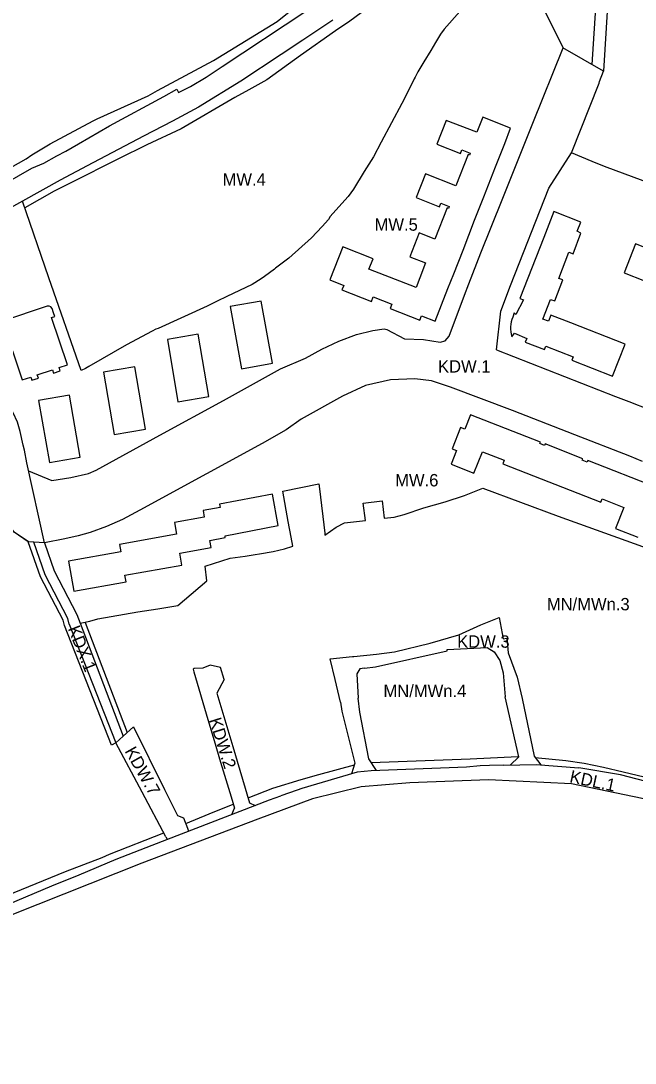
# Model space of a CAD drawing. Extents: x 7427074 to 7428708, y 5545888 to 5547145.
# Drawn here: x 7427353.4 to 7427601.2, y 5545928.9 to 5546349.6 of the extents above; entities that cross this region are included whole.
import ezdxf

# ---------------------------------------------------------------- set-up
doc = ezdxf.new("R2010")
doc.units = 0
for name, color, linetype in [('linie_rozgraniczajace', 7, 'Continuous'), ('linie_zabudowy_nieprzekraczalne', 7, 'Continuous'), ('linie_zabudowy_obowiazujace', 7, 'Continuous'), ('oznaczenia_przeznaczen', 7, 'Continuous')]:
    doc.layers.add(name, color=color, linetype=linetype)

msp = doc.modelspace()

# ---------------------------------------------------------------- linework, layer by layer
at = {"layer": 'linie_rozgraniczajace'}
for p, q in [((7427585.66, 5546361.85), (7427583.79, 5546331.94)), ((7427572.14, 5546338.65), (7427565.07, 5546353.09)), ((7427372.96, 5546106.11), (7427391.75, 5546058.22)), ((7427550.07, 5546094.44), (7427553.7, 5546084.74)), ((7427554.32, 5546052.55), (7427548.84, 5546076.69)), ((7427554.32, 5546052.55), (7427550.82, 5546049.17)), ((7427411.94, 5546020.17), (7427412.43, 5546019.25)), ((7427420.62, 5546023.79), (7427421.08, 5546022.57))]:
    msp.add_line(p, q, dxfattribs=at)
for points in [[(7427337.22, 5546278.25), (7427357.81, 5546290.12), (7427362.65, 5546292.17), (7427367.93, 5546295.03), (7427371.59, 5546297.02), (7427376.72, 5546299.98), (7427389.23, 5546307.22), (7427411.07, 5546319.08), (7427416.4, 5546321.96), (7427416.99, 5546320.6), (7427421.81, 5546323.13), (7427428.21, 5546326.84), (7427431.47, 5546329), (7427434.68, 5546331.13), (7427468.39, 5546353.49), (7427473.12, 5546356.61)], [(7427533.07, 5546355.02), (7427530.57, 5546353.37), (7427524.16, 5546346.19), (7427522.69, 5546344.23), (7427520.72, 5546340.78), (7427518.78, 5546337.59), (7427516.03, 5546333.03), (7427513.63, 5546329.06), (7427512.52, 5546326.87), (7427512.14, 5546326.11), (7427511.99, 5546325.8), (7427507.15, 5546316.17), (7427498.79, 5546300.65), (7427495.71, 5546294.66), (7427491.99, 5546288.77), (7427487.56, 5546281.59), (7427485.5, 5546278.63), (7427480.53, 5546273.21), (7427478.17, 5546270.58), (7427477.6, 5546269.37)], [(7427479.26, 5546349.84), (7427467.13, 5546341.73), (7427458.44, 5546335.98), (7427442.11, 5546325.17), (7427425.1, 5546314.77), (7427419.81, 5546311.95), (7427414.6, 5546309.15), (7427402.89, 5546302.98), (7427380.2, 5546291.01), (7427369.27, 5546285.25), (7427354.06, 5546276.83), (7427340.36, 5546269.25), (7427329.45, 5546262.24), (7427324.29, 5546258.02), (7427314.5, 5546248.22), (7427302.27, 5546235.33)], [(7427522.53, 5546219.87), (7427524.61, 5546220.41), (7427526.22, 5546222.33), (7427532.44, 5546238.87), (7427534.15, 5546243.49), (7427539.05, 5546255.95), (7427547.64, 5546277.34), (7427559.97, 5546308.24), (7427559.97, 5546308.24), (7427572.14, 5546338.65)], [(7427588.43, 5546329.27), (7427572.13, 5546338.64)], [(7427545.35, 5546216.74), (7427547.1, 5546232.35), (7427551, 5546242.8), (7427566.39, 5546281.99), (7427566.39, 5546281.99), (7427575.59, 5546296.26), (7427586.67, 5546324.49), (7427586.88, 5546325.05), (7427588.43, 5546329.27)], [(7427611.7, 5546285.64), (7427609.61, 5546286.47), (7427608.13, 5546283.63), (7427588.87, 5546290.82), (7427583.89, 5546292.85), (7427575.59, 5546296.26)], [(7427461.49, 5546253.86), (7427456.18, 5546249.77), (7427455.7, 5546249.39), (7427451.75, 5546246.46), (7427450.39, 5546245.44), (7427446.7, 5546243.13), (7427436.53, 5546238.36), (7427432.6, 5546236.41), (7427428.56, 5546234.41), (7427408.83, 5546225.47), (7427407.9, 5546225.14), (7427406.37, 5546224.31), (7427396.09, 5546218.8), (7427380.86, 5546210.07), (7427379.5, 5546209.28), (7427377.7, 5546208.41), (7427364.76, 5546245.84), (7427354.06, 5546276.83)], [(7427461.49, 5546253.86), (7427470.64, 5546261.96), (7427475.04, 5546266.64), (7427477.6, 5546269.37)], [(7427356.5, 5546167.98), (7427365.89, 5546164.1), (7427373.6, 5546165.22), (7427380.71, 5546166.91), (7427383.8, 5546168.26), (7427409.47, 5546182.38), (7427435.18, 5546196.31), (7427458.18, 5546209.1), (7427468.29, 5546213.44), (7427474.87, 5546217.06), (7427481.65, 5546220.35), (7427488.89, 5546222.98), (7427495.42, 5546224.54), (7427500.02, 5546225.27), (7427501.03, 5546225.04), (7427508.15, 5546221.25), (7427515.88, 5546220.93), (7427522.53, 5546219.87)], [(7427545.35, 5546216.74), (7427593.34, 5546198.01), (7427598.66, 5546195.91), (7427623.36, 5546186.25), (7427628.66, 5546184.17), (7427648.13, 5546176.53), (7427654.33, 5546174.53), (7427662.31, 5546171.58), (7427668.97, 5546168.95), (7427672, 5546169.44), (7427675.55, 5546167.81), (7427682.66, 5546163.4), (7427687.72, 5546158.91), (7427693.8, 5546151.78), (7427697.63, 5546146.12), (7427700.27, 5546141.2), (7427707.56, 5546142.3), (7427708.66, 5546134.98)], [(7427362.96, 5546138.85), (7427355.8, 5546171.15), (7427354.86, 5546176.31), (7427354.43, 5546178.33), (7427353.09, 5546183.9), (7427352.09, 5546187.59), (7427350.29, 5546191.37), (7427347.87, 5546195.85), (7427345.98, 5546198.7), (7427344.73, 5546200.27), (7427339.68, 5546206.95)], [(7427604.14, 5546171.77), (7427599.12, 5546173.84), (7427576.88, 5546182.47), (7427551.75, 5546192.25), (7427526.78, 5546201.78), (7427519.1, 5546204.23), (7427512.36, 5546205.13), (7427502.51, 5546204.73), (7427492.42, 5546202.43), (7427483.24, 5546198.03), (7427466.45, 5546188.79), (7427460.44, 5546184.49), (7427450.8, 5546179.04), (7427428.28, 5546166.72), (7427401.44, 5546152.06), (7427394.47, 5546148.34), (7427388.04, 5546145.49), (7427381.33, 5546143.11), (7427376.53, 5546141.73), (7427371.15, 5546140.49), (7427362.96, 5546138.85)], [(7427377.36, 5546106.5), (7427381.32, 5546107.29), (7427384.54, 5546108.16), (7427400.64, 5546110.99), (7427408.69, 5546112.29), (7427416.75, 5546113.59), (7427419.39, 5546115.87), (7427428.51, 5546123.51), (7427427.83, 5546129.43), (7427437.92, 5546132.65), (7427443.86, 5546133.45), (7427447.94, 5546134.15), (7427449.76, 5546134.46), (7427455.21, 5546135.39), (7427459.76, 5546136.47), (7427463.14, 5546137.54), (7427462.44, 5546141.22), (7427461.25, 5546147.47), (7427459.16, 5546159.69), (7427473.69, 5546162.73), (7427473.93, 5546160.74), (7427476.03, 5546142.76), (7427476.01, 5546142.03), (7427480.62, 5546145.18), (7427484.01, 5546147), (7427492.46, 5546147.96), (7427491.46, 5546154.88), (7427499.19, 5546155.82), (7427500.05, 5546148.87), (7427503.96, 5546149.31), (7427508.04, 5546150.34), (7427515.95, 5546153.04), (7427524.61, 5546155.47), (7427532.38, 5546158.06), (7427539.84, 5546160.95), (7427570.24, 5546149.62), (7427616.18, 5546133.08)], [(7427362.96, 5546138.85), (7427356.47, 5546139.32), (7427350.7, 5546143.17), (7427348.4, 5546146.53)], [(7427372.96, 5546106.11), (7427372.32, 5546108.36), (7427363.25, 5546125.96), (7427358.61, 5546139.16)], [(7427362.96, 5546138.85), (7427366.93, 5546127.55), (7427375.96, 5546110.02), (7427377.36, 5546106.5), (7427394.7, 5546060.93)], [(7427478.24, 5546092.13), (7427487.27, 5546092.97), (7427487.75, 5546093.02), (7427496.86, 5546093.93), (7427504.22, 5546094.97), (7427518.52, 5546098.4), (7427530.17, 5546101.83), (7427538.92, 5546105.81), (7427546.36, 5546108.7), (7427547.93, 5546100.15), (7427549.42, 5546100.41), (7427550.07, 5546094.44)], [(7427525.47, 5546095.28), (7427525.35, 5546095.82), (7427541.6, 5546096.62), (7427544.33, 5546094.87), (7427546.64, 5546091.44), (7427547.94, 5546086.43), (7427548.84, 5546076.69)], [(7427482.4, 5546074.59), (7427480.23, 5546083.72), (7427478.24, 5546092.13)], [(7427492.12, 5546088.31), (7427496.55, 5546088.86), (7427525.47, 5546095.28)], [(7427429.81, 5546089.56), (7427426.84, 5546088.32), (7427423.39, 5546088.15), (7427422.88, 5546087.91), (7427423.21, 5546086.78), (7427428.88, 5546067.65), (7427431.43, 5546059.05), (7427434.02, 5546050.4), (7427435.09, 5546046.83), (7427438.22, 5546036.36), (7427439.6, 5546031.75)], [(7427435.46, 5546083.73), (7427433.93, 5546088.56), (7427429.81, 5546089.56)], [(7427492.12, 5546088.31), (7427490.21, 5546088.07), (7427488.94, 5546085.99), (7427489.56, 5546076.25)], [(7427435.46, 5546083.73), (7427432.52, 5546078.24), (7427438.93, 5546056.71), (7427445.69, 5546033.97), (7427447.96, 5546032.89)], [(7427553.7, 5546084.74), (7427555.64, 5546076.1), (7427560.5, 5546052.85)], [(7427482.4, 5546074.59), (7427482.97, 5546070.97), (7427488.2, 5546049.98)], [(7427493.85, 5546051.68), (7427490.12, 5546070.58), (7427489.56, 5546076.25)], [(7427411.94, 5546020.17), (7427402.35, 5546038.25), (7427391.75, 5546058.22), (7427394.7, 5546060.93), (7427398.89, 5546064.63), (7427411.42, 5546039.31), (7427416.61, 5546028.81), (7427419.09, 5546027.88), (7427420.62, 5546023.79)], [(7427488.2, 5546049.98), (7427486.8, 5546045.69)], [(7427496.89, 5546046.96), (7427493.85, 5546051.68)], [(7427548.19, 5546049.12), (7427561.3, 5546049.38), (7427578.57, 5546048.02)], [(7427560.5, 5546052.85), (7427563.13, 5546049.24)], [(7427489.1, 5546046.38), (7427466.83, 5546039.69), (7427464.91, 5546039.12), (7427458.27, 5546036.72)], [(7427548.19, 5546049.12), (7427542.42, 5546049.02), (7427538.7, 5546048.83), (7427533.19, 5546048.34), (7427494.8, 5546046.88), (7427489.1, 5546046.38)], [(7427631.03, 5546036.17), (7427619.07, 5546038.93), (7427615.51, 5546039.97), (7427595.29, 5546045.21), (7427578.57, 5546048.02)], [(7427911.89, 5545928.89), (7427870.1, 5545938.24), (7427831.94, 5545947.85), (7427788.48, 5545964.44), (7427727.81, 5545988.89), (7427677.19, 5546010.17), (7427625.84, 5546029.97), (7427604.02, 5546035.69), (7427575.52, 5546041.68), (7427542.04, 5546043.19), (7427510.38, 5546042.02), (7427490.71, 5546040.43), (7427471.03, 5546035.51), (7427448.97, 5546027.41), (7427402.2, 5546009.67), (7427266.44, 5545955.68)], [(7427406.37, 5546016.93), (7427453.77, 5546035.12), (7427458.27, 5546036.72)], [(7427438.5, 5546029.26), (7427439.6, 5546031.75)], [(7427245.02, 5545955.38), (7427256.58, 5545957.63), (7427270.25, 5545962.61), (7427283.36, 5545968.11), (7427291.06, 5545970.44), (7427323.88, 5545982.69), (7427337.78, 5545988.56), (7427365.93, 5546000.51), (7427376.94, 5546004.95), (7427391.87, 5546011.19), (7427406.37, 5546016.93), (7427406.37, 5546016.93)]]:
    msp.add_lwpolyline(points, dxfattribs=at)
at = {"layer": 'linie_zabudowy_nieprzekraczalne'}
for p, q in [((7427389.97, 5546057.28), (7427371.06, 5546105.47)), ((7427391.75, 5546058.22), (7427389.97, 5546057.28))]:
    msp.add_line(p, q, dxfattribs=at)
for points in [[(7427751.37, 5546290.13), (7427756.55, 5546320.62), (7427757.64, 5546326.33), (7427758.11, 5546329.95), (7427758.57, 5546336.83), (7427758.82, 5546340.34), (7427759.43, 5546349.06), (7427735.84, 5546350.7), (7427713.25, 5546365.58), (7427659.2, 5546370.84), (7427656.06, 5546369.32), (7427642.12, 5546362.97), (7427642.11, 5546362.97), (7427633.54, 5546359.07), (7427621.01, 5546353.36), (7427620, 5546352.9), (7427590.07, 5546355.46), (7427588.43, 5546329.27)], [(7427495.65, 5546357.21), (7427490.69, 5546352.83), (7427486.19, 5546349.49), (7427480.4, 5546345.55), (7427466.21, 5546335.53), (7427452.71, 5546325.77), (7427445.38, 5546321.77), (7427439.81, 5546318.7), (7427418.08, 5546306.01), (7427404.24, 5546299.5), (7427392.77, 5546293.83), (7427373.57, 5546284.17), (7427366.91, 5546280.83), (7427354.99, 5546274.14)], [(7427257.14, 5546195.43), (7427285.02, 5546234.34), (7427290.57, 5546240.98), (7427293.76, 5546244.92), (7427305.32, 5546258.92), (7427313.52, 5546269.3), (7427316.86, 5546272.22), (7427340.92, 5546285.7), (7427355.54, 5546293.85), (7427357.88, 5546295.45), (7427365.28, 5546299.95), (7427382.65, 5546309.18), (7427384.23, 5546310.01), (7427404.8, 5546319.28), (7427408.61, 5546321.5), (7427431.21, 5546333.63), (7427456.78, 5546349.28), (7427464.99, 5546355.87)], [(7427356.43, 5546139.35), (7427350.7, 5546143.17), (7427348.4, 5546146.53)], [(7427371.06, 5546105.47), (7427370.45, 5546107.62), (7427361.41, 5546125.17), (7427356.43, 5546139.35)], [(7427379.4, 5546106.77), (7427396.3, 5546062.34)], [(7427466.56, 5546043.43), (7427473.57, 5546045.33), (7427487.97, 5546049.28)], [(7427494.8, 5546050.21), (7427534.62, 5546051.72), (7427553.9, 5546052.71)], [(7427560.88, 5546052.32), (7427573.21, 5546051.03), (7427580.61, 5546049.97), (7427588.46, 5546048.42), (7427596.37, 5546046.51), (7427607.64, 5546043.77)], [(7427445.11, 5546035.93), (7427455.03, 5546039.84), (7427466.56, 5546043.43)], [(7427419.92, 5546025.65), (7427429.39, 5546029.5), (7427439.11, 5546033.39)], [(7427386.29, 5546011.96), (7427389.13, 5546013.19), (7427411.05, 5546021.85)], [(7427323.35, 5545986.61), (7427371.5, 5546006.19), (7427386.29, 5546011.96)]]:
    msp.add_lwpolyline(points, dxfattribs=at)
at = {"layer": 'linie_zabudowy_obowiazujace'}
for p, q in [((7427514.37, 5546245.91), (7427512.85, 5546241.94)), ((7427433.77, 5546153.12), (7427426.94, 5546151.91)), ((7427416.16, 5546142.37), (7427393.18, 5546138.28)), ((7427393.18, 5546138.28), (7427393.73, 5546135.23)), ((7427393.73, 5546135.23), (7427372.62, 5546131.47))]:
    msp.add_line(p, q, dxfattribs=at)
for points in [[(7427525.69, 5546241.51), (7427528.08, 5546247.51), (7427531.8, 5546257.06), (7427536.49, 5546269.07), (7427540.19, 5546278.57), (7427544.89, 5546290.64), (7427548.6, 5546300.14), (7427551.01, 5546306.33), (7427539.73, 5546310.73), (7427537.33, 5546304.59), (7427525.03, 5546309.36), (7427521.29, 5546299.78), (7427530.81, 5546296.06), (7427531.33, 5546297.48), (7427534.68, 5546296.17), (7427534.39, 5546295.43), (7427533.83, 5546295.65), (7427528.89, 5546283.03), (7427516.64, 5546287.83), (7427512.86, 5546278.23), (7427522.31, 5546274.54), (7427522.85, 5546275.94), (7427526.24, 5546274.61), (7427525.96, 5546273.87), (7427525.41, 5546274.09), (7427520.48, 5546261.51), (7427514.09, 5546263.99), (7427510.35, 5546254.39), (7427516.72, 5546251.92), (7427514.37, 5546245.91)], [(7427512.85, 5546241.94), (7427493.86, 5546249.42), (7427495.53, 5546253.57), (7427483.34, 5546258.35), (7427478.1, 5546245), (7427483.69, 5546242.81), (7427482.98, 5546241.03), (7427494.9, 5546236.33), (7427495.6, 5546238.13), (7427503.05, 5546235.21), (7427502.37, 5546233.43), (7427514.33, 5546228.72), (7427515.01, 5546230.51), (7427520.61, 5546228.33), (7427525.69, 5546241.51)], [(7427610.23, 5546161.04), (7427582.13, 5546172.11), (7427581.89, 5546171.5), (7427579.89, 5546172.29), (7427580.11, 5546172.85), (7427564.94, 5546178.8), (7427564.7, 5546178.19), (7427562.82, 5546178.93), (7427563.04, 5546179.49), (7427534.81, 5546190.59), (7427532.51, 5546184.74), (7427530.84, 5546185.4), (7427527.46, 5546176.81), (7427529.15, 5546176.14), (7427526.97, 5546170.59), (7427536.17, 5546166.96), (7427539.6, 5546175.69), (7427548.36, 5546172.24), (7427547.81, 5546170.84), (7427587.36, 5546155.26), (7427587.91, 5546156.66), (7427596.64, 5546153.22), (7427593.28, 5546144.7), (7427602.33, 5546141.13)], [(7427435.81, 5546141.74), (7427457.23, 5546145.91), (7427454.91, 5546158.48), (7427433.52, 5546154.47), (7427433.77, 5546153.12)], [(7427426.94, 5546151.91), (7427427.41, 5546149.23), (7427415.36, 5546147.11), (7427416.16, 5546142.37)], [(7427417.54, 5546134.76), (7427430.15, 5546136.98), (7427429.64, 5546139.9), (7427435.91, 5546141.01), (7427435.81, 5546141.74)], [(7427395.41, 5546125.79), (7427418.43, 5546129.87), (7427417.54, 5546134.76)], [(7427372.62, 5546131.47), (7427374.78, 5546119.41), (7427395.88, 5546123.17), (7427395.41, 5546125.79)]]:
    msp.add_lwpolyline(points, dxfattribs=at)
for points in [[(7427557.49, 5546221.33), (7427556.92, 5546219.9), (7427564.68, 5546216.94), (7427565.21, 5546218.31), (7427570.75, 5546216.12), (7427576.22, 5546213.96), (7427575.74, 5546212.6), (7427592.08, 5546206.15), (7427597.18, 5546219.1), (7427575.29, 5546227.75), (7427567.26, 5546230.83), (7427566.3, 5546228.36), (7427564.01, 5546229.24), (7427567.11, 5546237.15), (7427568.77, 5546236.53), (7427572.05, 5546244.99), (7427570.39, 5546245.61), (7427574.53, 5546256.15), (7427576.2, 5546255.5), (7427579.39, 5546263.89), (7427577.82, 5546264.63), (7427579.32, 5546268.38), (7427568.5, 5546272.62), (7427564.4, 5546262.1), (7427554.78, 5546237.52), (7427556.18, 5546237), (7427553.06, 5546231.08), (7427552.48, 5546231.67), (7427551.84, 5546230.01), (7427551.5, 5546229.07), (7427551.25, 5546228.1), (7427551.08, 5546227.11), (7427550.98, 5546226.12), (7427550.96, 5546225.12), (7427551.03, 5546224.12), (7427551.16, 5546223.13), (7427551.44, 5546221.99), (7427552.56, 5546223.56)], [(7427601.39, 5546259.56), (7427596.79, 5546247.81), (7427613.18, 5546241.41), (7427612.51, 5546239.98), (7427629.37, 5546233.39), (7427629.91, 5546234.78), (7427633.47, 5546233.39), (7427632.91, 5546231.96), (7427649.75, 5546225.38), (7427650.28, 5546226.74), (7427666.68, 5546220.33), (7427671.34, 5546232.25)], [(7427353.99, 5546204.69), (7427357.4, 5546205.83), (7427357.84, 5546204.5), (7427360.5, 5546205.39), (7427360.06, 5546206.71), (7427366.18, 5546208.76), (7427366.62, 5546207.43), (7427369.28, 5546208.32), (7427368.83, 5546209.65), (7427372.25, 5546210.79), (7427365.85, 5546229.84), (7427367.09, 5546230.25), (7427366.57, 5546231.78), (7427366, 5546233.48), (7427365.57, 5546234.15), (7427364.84, 5546234.46), (7427364.11, 5546234.43), (7427346.05, 5546228.37)], [(7427450.31, 5546236.44), (7427437.89, 5546234.25), (7427442.5, 5546209.07), (7427454.95, 5546211.37)], [(7427412.56, 5546221.01), (7427416.78, 5546195.86), (7427429.2, 5546197.95), (7427424.98, 5546223.1)], [(7427386.83, 5546207.77), (7427391.1, 5546182.64), (7427403.75, 5546184.79), (7427399.47, 5546209.92)], [(7427360.59, 5546196.39), (7427364.97, 5546171.27), (7427377.39, 5546173.44), (7427373, 5546198.56)]]:
    msp.add_lwpolyline(points, close=True, dxfattribs=at)

# ---------------------------------------------------------------- texts
at = {"layer": 'oznaczenia_przeznaczen'}
for s, p in [('MW.4', (7427434.8, 5546283.08)), ('MW.5', (7427496.11, 5546264.87)), ('KDW.1', (7427521.71, 5546207.61)), ('MW.6', (7427504.42, 5546161.68)), ('MN/MWn.3', (7427565.6, 5546111.65)), ('KDW.3', (7427529.43, 5546096.56)), ('MN/MWn.4', (7427499.7, 5546076.61))]:
    msp.add_text(s, height=5, dxfattribs=at).set_placement(p)
for s, rotation, p in [('KDX.1', 291.5748, (7427372.32, 5546104.3)), ('KDW.2', 287.4965, (7427429.29, 5546067.44)), ('KDW.7', 299.2951, (7427395.21, 5546054.87)), ('KDL.1', 347.9685, (7427574.53, 5546042.32))]:
    msp.add_text(s, height=5, rotation=rotation, dxfattribs=at).set_placement(p)

doc.saveas('drawing.dxf')
